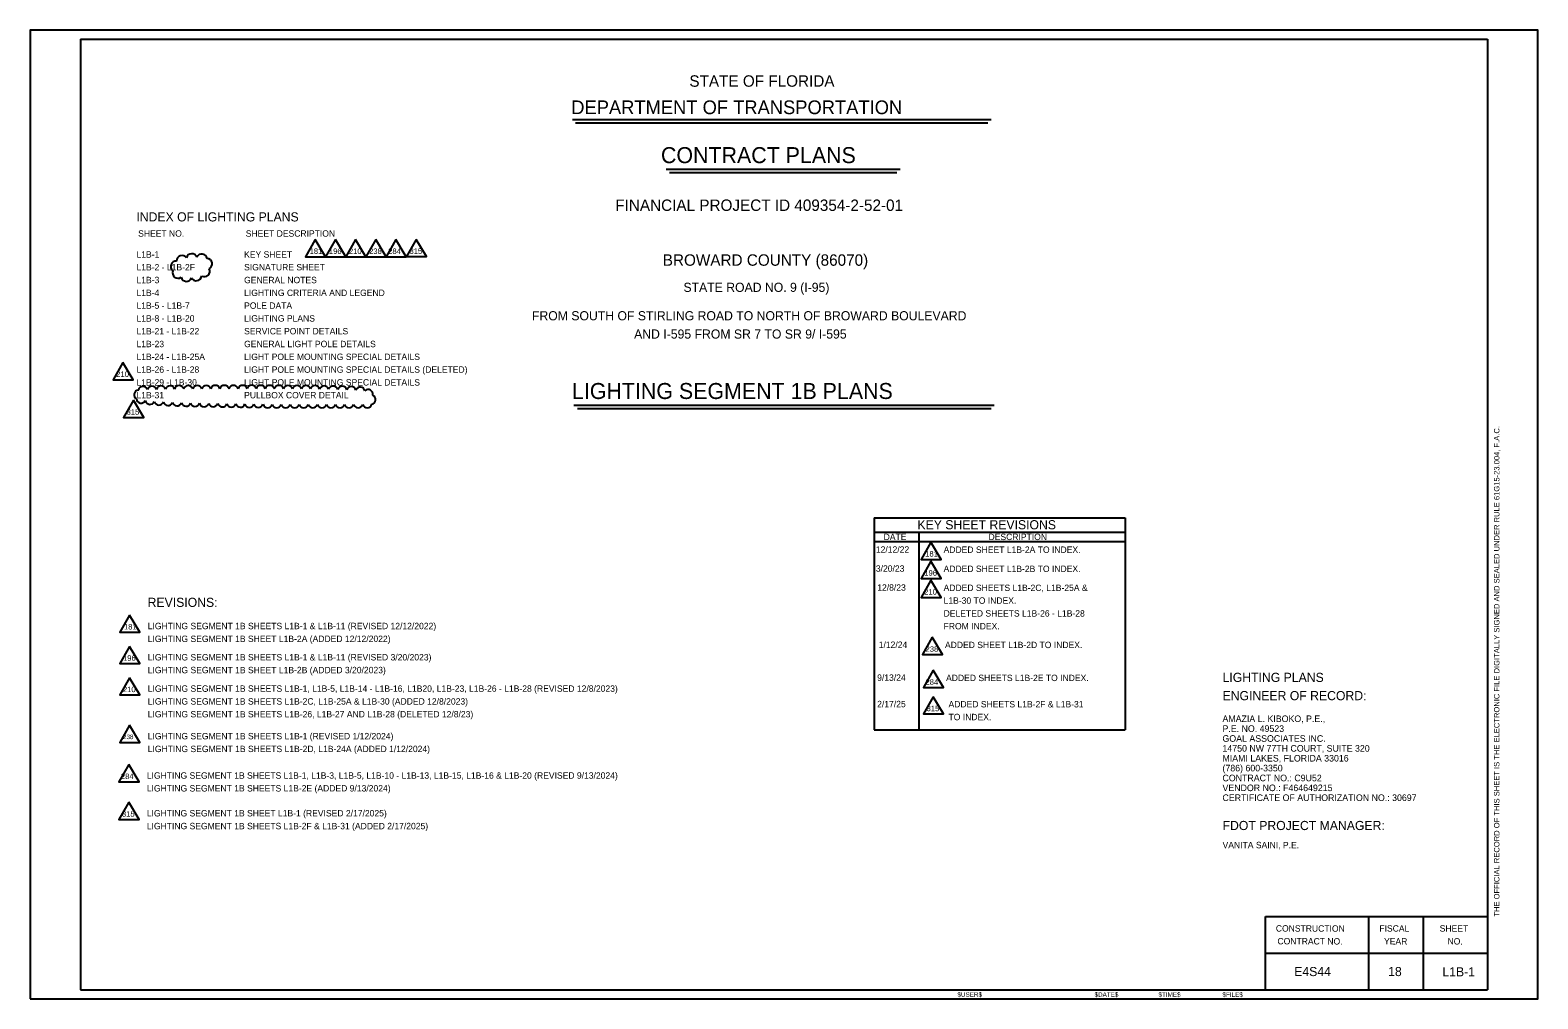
# Model space of a CAD drawing. Extents: x -818.6 to -802.1, y -2197.9 to -2175.
# Drawn here: x -818.56 to -802.06, y -2197.92 to -2187.32 of the extents above; entities that cross this region are included whole.
import ezdxf

# ---------------------------------------------------------------- set-up
doc = ezdxf.new("R2010")
doc.units = 0
for name, color, linetype in [('ActivePointCell_dp', 7, 'Continuous'), ('Cloud_dp', 7, 'Continuous'), ('PlotBorder_dp', 7, 'Continuous'), ('SheetBorder_dp', 7, 'Continuous'), ('SheetLines_dp', 7, 'Continuous'), ('SumBoxLines_dp', 7, 'Continuous'), ('TextLabel', 7, 'Continuous'), ('TextMinor', 7, 'Continuous'), ('TextMisc', 7, 'Continuous'), ('TextNotes', 7, 'Continuous'), ('TextShtNo', 7, 'Continuous'), ('TextTitle', 7, 'Continuous')]:
    doc.layers.add(name, color=color, linetype=linetype)

msp = doc.modelspace()

# ---------------------------------------------------------------- linework, layer by layer
at = {"layer": 'ActivePointCell_dp'}
msp.add_line((-802.614, -2187.419), (-802.614, -2187.419), dxfattribs=at)
at = {"layer": 'Cloud_dp'}
for points in [[(-815.443, -2189.61), (-815.551, -2189.798), (-815.33, -2189.798)], [(-815.222, -2189.61), (-815.33, -2189.798), (-815.109, -2189.798)], [(-815.002, -2189.61), (-815.109, -2189.798), (-814.889, -2189.798)], [(-814.781, -2189.61), (-814.889, -2189.798), (-814.668, -2189.798)], [(-814.56, -2189.61), (-814.667, -2189.798), (-814.447, -2189.798)], [(-814.339, -2189.609), (-814.446, -2189.797), (-814.226, -2189.797)], [(-817.548, -2190.956), (-817.656, -2191.145), (-817.435, -2191.145)], [(-817.434, -2191.369), (-817.542, -2191.557), (-817.321, -2191.557)], [(-808.706, -2192.922), (-808.814, -2193.11), (-808.593, -2193.11)], [(-808.706, -2193.13), (-808.814, -2193.318), (-808.593, -2193.318)], [(-808.706, -2193.338), (-808.814, -2193.526), (-808.593, -2193.526)], [(-817.475, -2193.719), (-817.583, -2193.907), (-817.362, -2193.907)], [(-808.691, -2193.963), (-808.799, -2194.151), (-808.578, -2194.151)], [(-817.475, -2194.062), (-817.583, -2194.25), (-817.362, -2194.25)], [(-808.68, -2194.324), (-808.787, -2194.512), (-808.567, -2194.512)], [(-817.475, -2194.405), (-817.583, -2194.593), (-817.362, -2194.593)], [(-808.68, -2194.613), (-808.787, -2194.801), (-808.567, -2194.801)], [(-817.475, -2194.924), (-817.583, -2195.113), (-817.362, -2195.113)], [(-817.485, -2195.356), (-817.593, -2195.544), (-817.372, -2195.544)], [(-817.485, -2195.768), (-817.593, -2195.957), (-817.372, -2195.957)]]:
    msp.add_lwpolyline(points, close=True, dxfattribs=at)
for centre, radius, start, end in [((-816.966, -2189.905), 0.0599, 86.9907, 231.9907), ((-816.902, -2189.845), 0.06, 35.4166, 180.4166), ((-816.795, -2189.825), 0.0599, 21.2778, 166.2778), ((-816.685, -2189.828), 0.0599, 9.9863, 154.9863), ((-816.632, -2189.877), 0.0599, 298.9542, 83.9542), ((-816.946, -2189.974), 0.0599, 159.4236, 304.4236), ((-816.854, -2190.008), 0.0599, 194.4381, 339.4381), ((-816.745, -2190.001), 0.0599, 207.5787, 352.5787), ((-816.657, -2189.957), 0.0599, 241.4449, 26.4449), ((-817.375, -2191.309), 0.0519, 94.7576, 239.7576), ((-817.349, -2191.348), 0.052, 186.6932, 331.6932), ((-817.329, -2191.27), 0.052, 20.2705, 165.2705), ((-817.23, -2191.267), 0.052, 19.1756, 164.1756), ((-817.131, -2191.264), 0.052, 18.6791, 163.6791), ((-817.032, -2191.262), 0.052, 18.3782, 163.3782), ((-816.933, -2191.261), 0.052, 18.1706, 163.1706), ((-816.834, -2191.26), 0.052, 18.0163, 163.0163), ((-816.735, -2191.259), 0.052, 17.8957, 162.8957), ((-816.635, -2191.259), 0.052, 17.7981, 162.7981), ((-816.536, -2191.258), 0.052, 17.717, 162.717), ((-816.437, -2191.258), 0.052, 17.6482, 162.6482), ((-816.338, -2191.258), 0.052, 17.5889, 162.5889), ((-816.239, -2191.258), 0.052, 17.5371, 162.5371), ((-816.14, -2191.257), 0.052, 17.4864, 162.4864), ((-816.04, -2191.258), 0.052, 17.4205, 162.4205), ((-815.941, -2191.258), 0.052, 17.3451, 162.3451), ((-815.842, -2191.258), 0.052, 17.2588, 162.2588), ((-815.743, -2191.259), 0.052, 17.1586, 162.1586), ((-815.644, -2191.259), 0.052, 17.0404, 162.0404), ((-815.545, -2191.26), 0.052, 16.898, 161.898), ((-815.446, -2191.261), 0.052, 16.7219, 161.7219), ((-815.347, -2191.263), 0.052, 16.4962, 161.4962), ((-815.248, -2191.265), 0.052, 16.192, 161.192), ((-815.149, -2191.268), 0.052, 15.7494, 160.7494), ((-815.05, -2191.271), 0.052, 15.0147, 160.0147), ((-814.951, -2191.277), 0.052, 13.3678, 158.3678), ((-814.865, -2191.303), 0.052, 348.0395, 133.0395), ((-814.835, -2191.361), 0.052, 281.0611, 66.0611), ((-817.253, -2191.362), 0.052, 192.0947, 337.0947), ((-817.154, -2191.369), 0.052, 193.8391, 338.8391), ((-817.055, -2191.375), 0.052, 194.7969, 339.7969), ((-816.957, -2191.379), 0.052, 195.4251, 340.4251), ((-816.858, -2191.382), 0.052, 195.8779, 340.8779), ((-816.759, -2191.385), 0.052, 196.2244, 341.2244), ((-816.659, -2191.387), 0.052, 196.4951, 341.4951), ((-816.56, -2191.388), 0.052, 196.5711, 341.5711), ((-816.461, -2191.39), 0.052, 196.5711, 341.5711), ((-816.362, -2191.392), 0.052, 196.5711, 341.5711), ((-816.263, -2191.393), 0.052, 196.5711, 341.5711), ((-816.164, -2191.395), 0.052, 196.5711, 341.5711), ((-816.065, -2191.396), 0.052, 196.5711, 341.5711), ((-815.965, -2191.398), 0.052, 196.5711, 341.5711), ((-815.866, -2191.399), 0.052, 197.0492, 342.0492), ((-815.767, -2191.4), 0.052, 197.5, 342.5), ((-815.668, -2191.4), 0.052, 197.5, 342.5), ((-815.569, -2191.4), 0.052, 197.5, 342.5), ((-815.47, -2191.4), 0.052, 197.5, 342.5), ((-815.371, -2191.4), 0.052, 197.5, 342.5), ((-815.272, -2191.4), 0.052, 197.5, 342.5), ((-815.172, -2191.4), 0.052, 197.5, 342.5), ((-815.073, -2191.4), 0.052, 197.5, 342.5), ((-814.974, -2191.4), 0.052, 197.5, 342.5), ((-814.875, -2191.398), 0.052, 199.2158, 344.2158)]:
    msp.add_arc(centre, radius, start, end, dxfattribs=at)
at = {"layer": 'PlotBorder_dp'}
msp.add_lwpolyline([(-818.564, -2197.919), (-802.064, -2197.919), (-802.064, -2187.319), (-818.564, -2187.319)], close=True, dxfattribs=at)
at = {"layer": 'SheetBorder_dp'}
for p, q in [((-818.014, -2187.419), (-818.014, -2197.819)), ((-818.014, -2187.419), (-802.614, -2187.419)), ((-802.614, -2187.419), (-802.614, -2197.819)), ((-818.014, -2197.819), (-802.614, -2197.819))]:
    msp.add_line(p, q, dxfattribs=at)
at = {"layer": 'SheetLines_dp'}
for p, q in [((-805.044, -2197.019), (-802.614, -2197.019)), ((-805.044, -2197.819), (-805.044, -2197.019)), ((-803.914, -2197.819), (-803.914, -2197.019)), ((-803.314, -2197.819), (-803.314, -2197.019)), ((-805.044, -2197.419), (-802.614, -2197.419))]:
    msp.add_line(p, q, dxfattribs=at)
at = {"layer": 'SumBoxLines_dp'}
for p, q in [((-809.327, -2192.654), (-809.327, -2194.975)), ((-809.327, -2192.654), (-806.58, -2192.654)), ((-806.58, -2192.654), (-806.58, -2194.975)), ((-809.327, -2192.814), (-806.58, -2192.814)), ((-808.837, -2192.814), (-808.837, -2194.975)), ((-809.327, -2192.914), (-806.58, -2192.914)), ((-809.327, -2194.975), (-806.58, -2194.975))]:
    msp.add_line(p, q, dxfattribs=at)
at = {"layer": 'TextTitle'}
for p, q in [((-812.63, -2188.295), (-808.048, -2188.295)), ((-812.597, -2188.333), (-808.083, -2188.333)), ((-811.605, -2188.84), (-809.044, -2188.84)), ((-811.566, -2188.878), (-809.077, -2188.878)), ((-812.614, -2191.421), (-808.015, -2191.421)), ((-812.575, -2191.459), (-808.047, -2191.459))]:
    msp.add_line(p, q, dxfattribs=at)

# ---------------------------------------------------------------- texts
at = {"layer": 'Cloud_dp'}
for s, height, p in [('181', 0.06, (-815.505, -2189.768)), ('196', 0.06, (-815.294, -2189.768)), ('210', 0.06, (-815.075, -2189.768)), ('238', 0.06, (-814.854, -2189.768)), ('284', 0.06, (-814.645, -2189.768)), ('315', 0.06, (-814.412, -2189.767)), ('210', 0.06, (-817.621, -2191.114)), ('315', 0.06, (-817.508, -2191.527)), ('181', 0.06, (-808.768, -2193.079)), ('196', 0.06, (-808.778, -2193.288)), ('210', 0.06, (-808.779, -2193.496)), ('181', 0.06, (-817.537, -2193.877)), ('196', 0.06, (-817.547, -2194.22)), ('238', 0.06, (-808.764, -2194.121)), ('284', 0.06, (-808.765, -2194.482)), ('210', 0.06, (-817.548, -2194.563)), ('315', 0.06, (-808.753, -2194.771)), ('238', 0.05, (-817.548, -2195.077)), ('284', 0.06, (-817.57, -2195.514)), ('315', 0.06, (-817.559, -2195.926))]:
    msp.add_text(s, height=height, rotation=0, dxfattribs=at).set_placement(p)
at = {"layer": 'TextLabel'}
for s, height, p in [('FINANCIAL PROJECT ID 409354-2-52-01', 0.125, (-812.16, -2189.297)), ('INDEX OF LIGHTING PLANS', 0.1, (-817.401, -2189.412)), ('L1B-1', 0.07, (-817.4, -2189.808)), ('L1B-2 - L1B-2F', 0.07, (-817.4, -2189.948)), ('SIGNATURE SHEET', 0.07, (-816.222, -2189.948)), ('KEY SHEET', 0.07, (-816.222, -2189.808)), ('BROWARD COUNTY (86070)', 0.125, (-811.64, -2189.897)), ('L1B-3', 0.07, (-817.4, -2190.088)), ('GENERAL NOTES', 0.07, (-816.222, -2190.088)), ('L1B-4', 0.07, (-817.4, -2190.228)), ('LIGHTING CRITERIA AND LEGEND', 0.07, (-816.222, -2190.228)), ('STATE ROAD NO. 9 (I-95)', 0.1, (-811.414, -2190.183)), ('L1B-5 - L1B-7', 0.07, (-817.4, -2190.368)), ('POLE DATA', 0.07, (-816.222, -2190.368)), ('L1B-8 - L1B-20', 0.07, (-817.4, -2190.508)), ('LIGHTING PLANS', 0.07, (-816.222, -2190.508)), ('FROM SOUTH OF STIRLING ROAD TO NORTH OF BROWARD BOULEVARD', 0.1, (-813.072, -2190.494)), ('L1B-21 - L1B-22', 0.07, (-817.4, -2190.648)), ('SERVICE POINT DETAILS', 0.07, (-816.222, -2190.648)), ('AND I-595 FROM SR 7 TO SR 9/ I-595', 0.1, (-811.954, -2190.694)), ('L1B-23', 0.07, (-817.4, -2190.788)), ('L1B-24 - L1B-25A', 0.07, (-817.4, -2190.928)), ('GENERAL LIGHT POLE DETAILS', 0.07, (-816.222, -2190.788)), ('LIGHT POLE MOUNTING SPECIAL DETAILS', 0.07, (-816.222, -2190.928)), ('L1B-26 - L1B-28', 0.07, (-817.4, -2191.068)), ('LIGHT POLE MOUNTING SPECIAL DETAILS (DELETED)', 0.07, (-816.222, -2191.068)), ('L1B-29 -L1B-30', 0.07, (-817.4, -2191.208)), ('LIGHT POLE MOUNTING SPECIAL DETAILS', 0.07, (-816.222, -2191.208)), ('L1B-31', 0.07, (-817.4, -2191.348)), ('PULLBOX COVER DETAIL', 0.07, (-816.222, -2191.348)), ('KEY SHEET REVISIONS', 0.1, (-808.853, -2192.781)), ('REVISIONS:', 0.1, (-817.278, -2193.63)), ('LIGHTING PLANS', 0.1, (-805.514, -2194.451)), ('ENGINEER OF RECORD:', 0.1, (-805.514, -2194.651)), ('AMAZIA L. KIBOKO, P.E.,', 0.07202, (-805.515, -2194.89)), ('P.E. NO. 49523', 0.07202, (-805.515, -2194.998)), ('GOAL ASSOCIATES INC. ', 0.07202, (-805.515, -2195.106)), ('14750 NW 77TH COURT, SUITE 320', 0.07202, (-805.515, -2195.214)), ('MIAMI LAKES, FLORIDA 33016', 0.07202, (-805.515, -2195.322)), ('CONTRACT NO.: C9U52', 0.07202, (-805.515, -2195.538)), ('(786) 600-3350', 0.07202, (-805.515, -2195.43)), ('VENDOR NO.: F464649215', 0.07202, (-805.515, -2195.646)), ('CERTIFICATE OF AUTHORIZATION NO.: 30697', 0.07202, (-805.515, -2195.754)), ('E4S44', 0.1, (-804.73, -2197.67)), ('18', 0.1, (-803.702, -2197.67))]:
    msp.add_text(s, height=height, dxfattribs=at).set_placement(p)
at = {"layer": 'TextMinor'}
for s, height, p in [('12/12/22', 0.07, (-809.308, -2193.037)), ('ADDED SHEET L1B-2A TO INDEX.', 0.07, (-808.567, -2193.039)), ('3/20/23', 0.07, (-809.308, -2193.245)), ('ADDED SHEET L1B-2B TO INDEX.', 0.07, (-808.567, -2193.248)), ('12/8/23', 0.07, (-809.293, -2193.453)), ('ADDED SHEETS L1B-2C, L1B-25A & ', 0.07, (-808.567, -2193.456)), ('L1B-30 TO INDEX.', 0.07, (-808.567, -2193.596)), ('DELETED SHEETS L1B-26 - L1B-28 ', 0.07, (-808.567, -2193.736)), ('FROM INDEX.', 0.07, (-808.567, -2193.876)), ('1/12/24', 0.07, (-809.277, -2194.079)), ('ADDED SHEET L1B-2D TO INDEX.', 0.07, (-808.552, -2194.081)), ('9/13/24', 0.07, (-809.294, -2194.439)), ('ADDED SHEETS L1B-2E TO INDEX.', 0.07, (-808.54, -2194.442)), ('2/17/25', 0.07, (-809.294, -2194.728)), ('ADDED SHEETS L1B-2F & L1B-31      ', 0.07, (-808.513, -2194.73)), ('TO INDEX.', 0.07, (-808.513, -2194.87)), ('$USER$', 0.05, (-808.415, -2197.897))]:
    msp.add_text(s, height=height, dxfattribs=at).set_placement(p)
for s, p in [('$DATE$', (-806.915, -2197.897)), ('$TIME$', (-806.215, -2197.897)), ('$FILE$', (-805.515, -2197.897))]:
    msp.add_text(s, height=0.05, rotation=360, dxfattribs=at).set_placement(p)
at = {"layer": 'TextMisc'}
msp.add_text('THE OFFICIAL RECORD OF THIS SHEET IS THE ELECTRONIC FILE DIGITALLY SIGNED AND SEALED UNDER RULE 61G15-23.004, F.A.C.', height=0.06, rotation=90, dxfattribs=at).set_placement((-802.484, -2197.019))
at = {"layer": 'TextNotes'}
for s, height, p in [('SHEET NO.', 0.07, (-817.382, -2189.579)), ('SHEET DESCRIPTION', 0.07, (-816.204, -2189.579)), ('DATE', 0.07, (-809.223, -2192.899)), ('DESCRIPTION', 0.07, (-808.075, -2192.899)), ('LIGHTING SEGMENT 1B SHEETS L1B-1 & L1B-11 (REVISED 12/12/2022)', 0.06998, (-817.277, -2193.874)), ('LIGHTING SEGMENT 1B SHEET L1B-2A (ADDED 12/12/2022)', 0.06998, (-817.277, -2194.014)), ('LIGHTING SEGMENT 1B SHEETS L1B-1 & L1B-11 (REVISED 3/20/2023)', 0.06998, (-817.277, -2194.216)), ('LIGHTING SEGMENT 1B SHEET L1B-2B (ADDED 3/20/2023)', 0.06998, (-817.277, -2194.356)), ('LIGHTING SEGMENT 1B SHEETS L1B-1, L1B-5, L1B-14 - L1B-16, L1B20, L1B-23, L1B-26 - L1B-28 (REVISED 12/8/2023)', 0.069982, (-817.277, -2194.559)), ('LIGHTING SEGMENT 1B SHEETS L1B-2C, L1B-25A & L1B-30 (ADDED 12/8/2023)', 0.06998, (-817.277, -2194.699)), ('LIGHTING SEGMENT 1B SHEETS L1B-26, L1B-27 AND L1B-28 (DELETED 12/8/23)', 0.06998, (-817.277, -2194.839)), ('LIGHTING SEGMENT 1B SHEETS L1B-1 (REVISED 1/12/2024)', 0.06998, (-817.277, -2195.079)), ('LIGHTING SEGMENT 1B SHEETS L1B-2D, L1B-24A (ADDED 1/12/2024)', 0.06998, (-817.277, -2195.219)), ('LIGHTING SEGMENT 1B SHEETS L1B-1, L1B-3, L1B-5, L1B-10 - L1B-13, L1B-15, L1B-16 & L1B-20 (REVISED 9/13/2024)', 0.069982, (-817.287, -2195.51)), ('LIGHTING SEGMENT 1B SHEETS L1B-2E (ADDED 9/13/2024)', 0.06998, (-817.287, -2195.65)), ('LIGHTING SEGMENT 1B SHEET L1B-1 (REVISED 2/17/2025)', 0.06998, (-817.287, -2195.923)), ('FDOT PROJECT MANAGER:', 0.1, (-805.514, -2196.072)), ('LIGHTING SEGMENT 1B SHEETS L1B-2F & L1B-31 (ADDED 2/17/2025)', 0.06998, (-817.287, -2196.063)), ('VANITA SAINI, P.E.', 0.07, (-805.514, -2196.271))]:
    msp.add_text(s, height=height, dxfattribs=at).set_placement(p)
for s, p in [('CONSTRUCTION', (-804.931, -2197.183)), ('FISCAL', (-803.798, -2197.183)), ('SHEET', (-803.138, -2197.183)), ('CONTRACT NO.', (-804.913, -2197.323)), ('YEAR', (-803.747, -2197.324)), ('NO.', (-803.052, -2197.324))]:
    msp.add_text(s, height=0.07, rotation=359.8607, dxfattribs=at).set_placement(p)
at = {"layer": 'TextShtNo'}
msp.add_text('L1B-1', height=0.1, dxfattribs=at).set_placement((-803.108, -2197.673))
at = {"layer": 'TextTitle'}
for s, height, p in [('STATE OF FLORIDA', 0.125, (-811.349, -2187.938)), ('DEPARTMENT OF TRANSPORTATION', 0.15, (-812.642, -2188.238)), ('CONTRACT PLANS', 0.175, (-811.66, -2188.774)), ('LIGHTING SEGMENT 1B PLANS', 0.175, (-812.634, -2191.355))]:
    msp.add_text(s, height=height, dxfattribs=at).set_placement(p)

doc.saveas('drawing.dxf')
